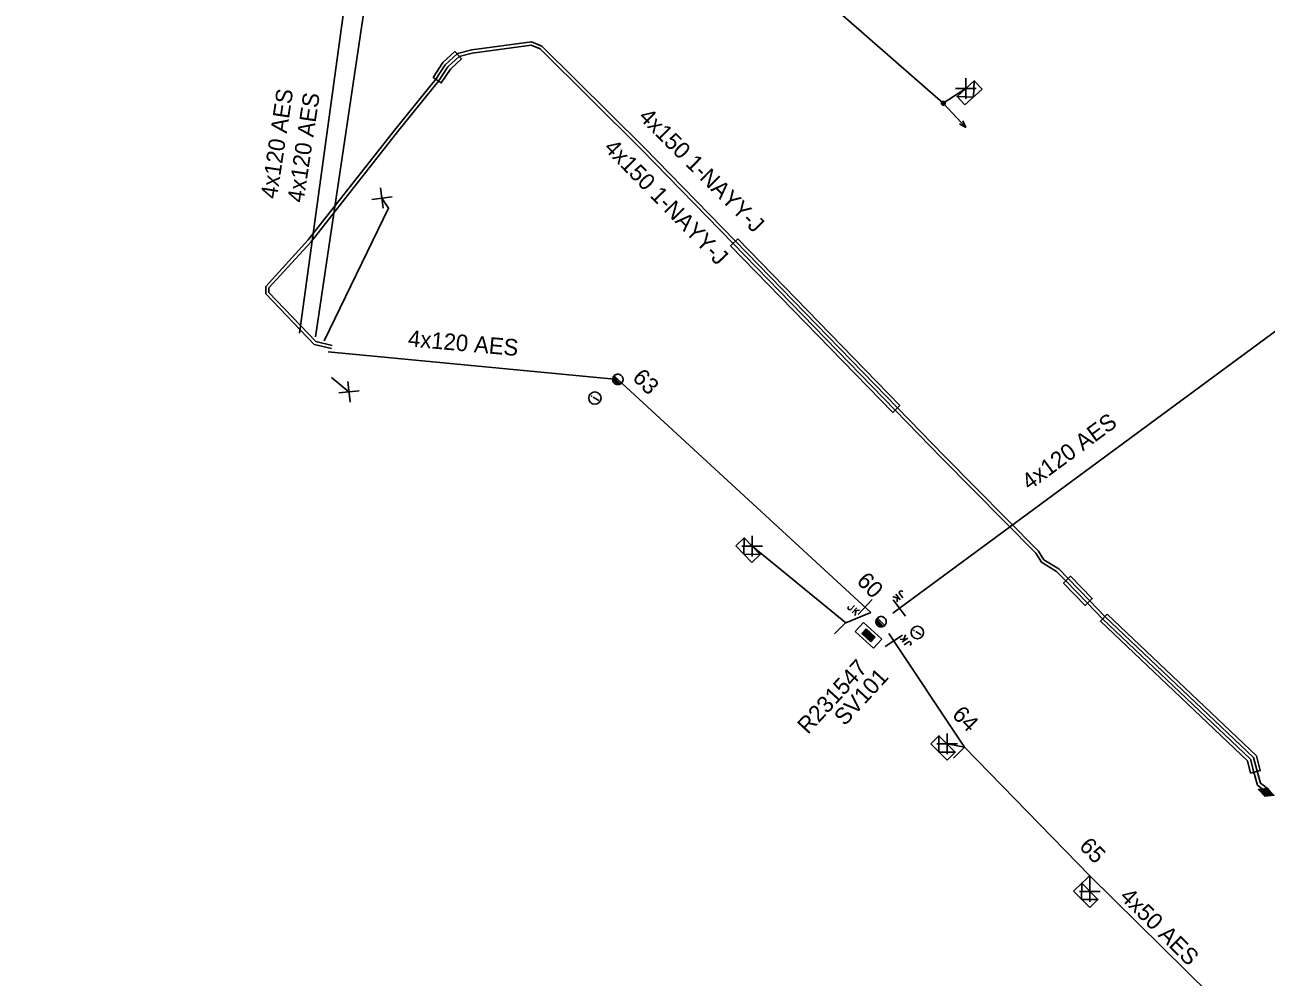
# Model space of a CAD drawing. Extents: x -544780 to -541582, y -1198995 to -1196551.
# Drawn here: x -543819.5 to -543744.4, y -1197448.1 to -1197390.4 of the extents above; entities that cross this region are included whole.
import ezdxf

# ---------------------------------------------------------------- set-up
doc = ezdxf.new("R2010")
doc.units = 0
for name, color, linetype in [('Vrstva 1', 7, 'Continuous'), ('Vrstva 10', 7, 'Continuous'), ('Vrstva 13', 7, 'Continuous'), ('Vrstva 14', 7, 'Continuous'), ('Vrstva 15', 7, 'Continuous'), ('Vrstva 18', 7, 'Continuous'), ('Vrstva 19', 7, 'Continuous'), ('Vrstva 2', 7, 'Continuous'), ('Vrstva 20', 7, 'Continuous'), ('Vrstva 28', 7, 'Continuous'), ('Vrstva 29', 7, 'Continuous'), ('Vrstva 30', 7, 'Continuous'), ('Vrstva 31', 7, 'Continuous'), ('Vrstva 34', 7, 'Continuous'), ('Vrstva 36', 7, 'Continuous'), ('Vrstva 4', 7, 'Continuous'), ('Vrstva 5', 7, 'Continuous'), ('Vrstva 50', 7, 'Continuous'), ('Vrstva 51', 7, 'Continuous'), ('Vrstva 54', 7, 'Continuous'), ('Vrstva 59', 7, 'Continuous'), ('Vrstva 6', 7, 'Continuous'), ('Vrstva 8', 7, 'Continuous'), ('Vrstva 9', 7, 'Continuous')]:
    doc.layers.add(name, color=color, linetype=linetype)

# ---------------------------------------------------------------- blocks, each defined once
blk = doc.blocks.new('NN440')
at = {"layer": 'Vrstva 2'}
for points in [[(0.63, 0), (0.63, 0.06), (0.62, 0.13), (0.6, 0.19), (0.58, 0.25), (0.55, 0.31), (0.51, 0.37), (0.47, 0.42), (0.42, 0.46), (0.37, 0.51), (0.32, 0.54), (0.26, 0.57), (0.2, 0.59), (0.13, 0.61), (0.07, 0.62), (0, 0.63), (-0.06, 0.62), (-0.13, 0.61), (-0.19, 0.59), (-0.26, 0.57), (-0.31, 0.54), (-0.37, 0.51), (-0.42, 0.46), (-0.47, 0.42), (-0.51, 0.37), (-0.54, 0.31), (-0.57, 0.25), (-0.6, 0.19), (-0.62, 0.13), (-0.63, 0.06), (-0.63, 0), (-0.63, -0.07), (-0.62, -0.14), (-0.6, -0.2), (-0.57, -0.26), (-0.54, -0.32), (-0.51, -0.37), (-0.47, -0.43), (-0.42, -0.47), (-0.37, -0.51), (-0.31, -0.55), (-0.26, -0.58), (-0.19, -0.6), (-0.13, -0.62), (-0.06, -0.63), (0, -0.63), (0.07, -0.63), (0.13, -0.62), (0.2, -0.6), (0.26, -0.58), (0.32, -0.55), (0.37, -0.51), (0.42, -0.47), (0.47, -0.43), (0.51, -0.37), (0.55, -0.32), (0.58, -0.26), (0.6, -0.2), (0.62, -0.14), (0.63, -0.07), (0.63, 0)], [(-0.63, 0), (0.63, 0)], [(-0.6, -0.18), (0.57, -0.18)], [(-0.51, -0.32), (0.5, -0.32)], [(-0.37, -0.47), (0.35, -0.47)]]:
    blk.add_lwpolyline(points, dxfattribs=at)
blk = doc.blocks.new('NN560')
at = {"layer": 'Vrstva 2'}
for points in [[(1.999, -0.001), (1.59, 0.141)], [(0, -0.001), (1.999, -0.001)], [(1.999, -0.001), (1.59, -0.134)]]:
    blk.add_lwpolyline(points, dxfattribs=at)
blk = doc.blocks.new('NN840')
at = {"layer": 'Vrstva 15'}
for points in [[(0.003, 0.619), (0.003, -0.631)], [(-0.745, -0.71), (-0.745, -0.66)], [(-0.73, -0.764), (-0.745, -0.71)], [(-0.538, -0.71), (-0.558, -0.764)], [(-0.538, -0.385), (-0.538, -0.71)], [(-0.332, -0.385), (-0.332, -0.798)], [(-0.332, -0.641), (-0.125, -0.385)], [(-0.263, -0.557), (-0.091, -0.798)], [(-0.657, -0.798), (-0.73, -0.764)], [(-0.627, -0.798), (-0.657, -0.798)], [(-0.558, -0.764), (-0.627, -0.798)]]:
    blk.add_lwpolyline(points, dxfattribs=at)
blk = doc.blocks.new('NN770')
at = {"layer": 'Vrstva 10'}
for p, q in [((0.002, 0.187), (0.002, 0.263)), ((0.002, -0.276), (0.002, 0.111))]:
    blk.add_line(p, q, dxfattribs=at)
blk.add_circle((0, -0.008), 0.375, dxfattribs=at)
blk = doc.blocks.new('NN870')
at = {"layer": 'Vrstva 4'}
for points in [[(0, -0.251), (0.5, 0.001), (0, 0.249), (-0.5, 0.001), (0, -0.251)], [(0.37, -0.003), (0, 0.186), (-0.362, 0.001), (0, -0.188), (0.37, -0.003)], [(0.245, -0.003), (0, 0.123), (-0.252, -0.003), (0, -0.125), (0.245, -0.003)], [(0.122, -0.003), (0, 0.06), (-0.13, -0.003), (0, -0.062), (0.122, -0.003)]]:
    blk.add_lwpolyline(points, dxfattribs=at)
blk = doc.blocks.new('NN800')
at = {"layer": 'Vrstva 1'}
for points in [[(-0.442, 0.442), (0.442, -0.442)], [(-0.442, -0.442), (0.442, 0.442)]]:
    blk.add_lwpolyline(points, dxfattribs=at)
blk = doc.blocks.new('NN620')
at = {"layer": 'Vrstva 8'}
for points in [[(0.752, 0.004), (-0.748, 0.004)], [(-0.748, 0.004), (-0.748, -0.746)], [(0.752, -0.746), (0.752, 0.004)], [(-0.748, -0.746), (0.752, -0.746)], [(0.368, -0.18), (-0.376, -0.18)], [(-0.376, -0.18), (-0.376, -0.558)], [(-0.376, -0.558), (0.368, -0.558)], [(0.321, -0.227), (-0.329, -0.227)], [(-0.329, -0.227), (-0.329, -0.51)], [(-0.329, -0.51), (0.321, -0.51)], [(0.274, -0.274), (-0.281, -0.274)], [(-0.281, -0.274), (-0.281, -0.463)], [(-0.281, -0.463), (0.274, -0.463)], [(0.227, -0.321), (-0.234, -0.321)], [(-0.234, -0.321), (-0.234, -0.416)], [(-0.234, -0.416), (0.227, -0.416)], [(-0.193, -0.369), (0.185, -0.369)], [(0.227, -0.416), (0.227, -0.321)], [(0.274, -0.463), (0.274, -0.274)], [(0.321, -0.51), (0.321, -0.227)], [(0.368, -0.558), (0.368, -0.18)]]:
    blk.add_lwpolyline(points, dxfattribs=at)
blk = doc.blocks.new('NN630')
at = {"layer": 'Vrstva 9'}
for points in [[(-0.003, -0.7), (-0.703, 0)], [(-0.703, -0.7), (-0.703, 0), (0.697, 0), (0.697, -0.7)], [(-0.703, -0.7), (0.697, -0.7)], [(-0.003, -0.7), (0.697, 0)]]:
    blk.add_lwpolyline(points, dxfattribs=at)
blk = doc.blocks.new('NN500')
at = {"layer": 'Vrstva 2'}
for points in [[(0, -0.24), (0.02, -0.23), (0.05, -0.23), (0.07, -0.22), (0.09, -0.22), (0.12, -0.2), (0.14, -0.19), (0.16, -0.18), (0.17, -0.16), (0.19, -0.14), (0.2, -0.12), (0.21, -0.1), (0.22, -0.07), (0.23, -0.05), (0.23, -0.02), (0.23, 0), (0.23, 0.02), (0.23, 0.05), (0.22, 0.07), (0.21, 0.1), (0.2, 0.12), (0.19, 0.14), (0.17, 0.16), (0.16, 0.17), (0.14, 0.19), (0.12, 0.2), (0.09, 0.21), (0.07, 0.22), (0.05, 0.23), (0.02, 0.23), (0, 0.23), (-0.03, 0.23), (-0.05, 0.23), (-0.07, 0.22), (-0.1, 0.21), (-0.12, 0.2), (-0.14, 0.19), (-0.16, 0.17), (-0.18, 0.16), (-0.19, 0.14), (-0.2, 0.12), (-0.22, 0.1), (-0.22, 0.07), (-0.23, 0.05), (-0.23, 0.02), (-0.24, 0), (-0.23, -0.02), (-0.23, -0.05), (-0.22, -0.07), (-0.22, -0.1), (-0.2, -0.12), (-0.19, -0.14), (-0.18, -0.16), (-0.16, -0.18), (-0.14, -0.19), (-0.12, -0.2), (-0.1, -0.22), (-0.07, -0.22), (-0.05, -0.23), (-0.03, -0.23), (0, -0.24)], [(0, -0.24), (0.02, -0.23), (0.05, -0.23), (0.07, -0.22), (0.09, -0.22), (0.12, -0.2), (0.14, -0.19), (0.16, -0.18), (0.17, -0.16), (0.19, -0.14), (0.2, -0.12), (0.21, -0.1), (0.22, -0.07), (0.23, -0.05), (0.23, -0.02), (0.23, 0), (0.23, 0.02), (0.23, 0.05), (0.22, 0.07), (0.21, 0.1), (0.2, 0.12), (0.19, 0.14), (0.17, 0.16), (0.16, 0.17), (0.14, 0.19), (0.12, 0.2), (0.09, 0.21), (0.07, 0.22), (0.05, 0.23), (0.02, 0.23), (0, 0.23), (-0.03, 0.23), (-0.05, 0.23), (-0.07, 0.22), (-0.1, 0.21), (-0.12, 0.2), (-0.14, 0.19), (-0.16, 0.17), (-0.18, 0.16), (-0.19, 0.14), (-0.2, 0.12), (-0.22, 0.1), (-0.22, 0.07), (-0.23, 0.05), (-0.23, 0.02), (-0.24, 0), (-0.23, -0.02), (-0.23, -0.05), (-0.22, -0.07), (-0.22, -0.1), (-0.2, -0.12), (-0.19, -0.14), (-0.18, -0.16), (-0.16, -0.18), (-0.14, -0.19), (-0.12, -0.2), (-0.1, -0.22), (-0.07, -0.22), (-0.05, -0.23), (-0.03, -0.23), (0, -0.24)], [(0, -0.21), (0.02, -0.2), (0.04, -0.2), (0.06, -0.2), (0.08, -0.19), (0.1, -0.18), (0.12, -0.17), (0.14, -0.15), (0.15, -0.14), (0.16, -0.12), (0.18, -0.1), (0.19, -0.08), (0.19, -0.06), (0.2, -0.04), (0.2, -0.02), (0.2, 0), (0.2, 0.02), (0.2, 0.04), (0.19, 0.06), (0.19, 0.08), (0.18, 0.1), (0.16, 0.12), (0.15, 0.14), (0.14, 0.15), (0.12, 0.17), (0.1, 0.18), (0.08, 0.19), (0.06, 0.19), (0.04, 0.2), (0.02, 0.2), (0, 0.2), (-0.02, 0.2), (-0.04, 0.2), (-0.06, 0.19), (-0.08, 0.19), (-0.1, 0.18), (-0.12, 0.17), (-0.14, 0.15), (-0.15, 0.14), (-0.17, 0.12), (-0.18, 0.1), (-0.19, 0.08), (-0.2, 0.06), (-0.2, 0.04), (-0.21, 0.02), (-0.21, 0), (-0.21, -0.02), (-0.2, -0.04), (-0.2, -0.06), (-0.19, -0.08), (-0.18, -0.1), (-0.17, -0.12), (-0.15, -0.14), (-0.14, -0.15), (-0.12, -0.17), (-0.1, -0.18), (-0.08, -0.19), (-0.06, -0.2), (-0.04, -0.2), (-0.02, -0.2), (0, -0.21)], [(0, -0.18), (0.02, -0.18), (0.04, -0.17), (0.05, -0.17), (0.07, -0.16), (0.09, -0.15), (0.1, -0.14), (0.12, -0.13), (0.13, -0.12), (0.14, -0.1), (0.15, -0.09), (0.16, -0.07), (0.17, -0.05), (0.17, -0.04), (0.17, -0.02), (0.17, 0), (0.17, 0.02), (0.17, 0.04), (0.17, 0.05), (0.16, 0.07), (0.15, 0.09), (0.14, 0.1), (0.13, 0.12), (0.12, 0.13), (0.1, 0.14), (0.09, 0.15), (0.07, 0.16), (0.05, 0.17), (0.04, 0.17), (0.02, 0.17), (0, 0.18), (-0.02, 0.17), (-0.04, 0.17), (-0.06, 0.17), (-0.07, 0.16), (-0.09, 0.15), (-0.1, 0.14), (-0.12, 0.13), (-0.13, 0.12), (-0.14, 0.1), (-0.15, 0.09), (-0.16, 0.07), (-0.17, 0.05), (-0.17, 0.04), (-0.18, 0.02), (-0.18, 0), (-0.18, -0.02), (-0.17, -0.04), (-0.17, -0.05), (-0.16, -0.07), (-0.15, -0.09), (-0.14, -0.1), (-0.13, -0.12), (-0.12, -0.13), (-0.1, -0.14), (-0.09, -0.15), (-0.07, -0.16), (-0.06, -0.17), (-0.04, -0.17), (-0.02, -0.18), (0, -0.18)], [(0, -0.15), (0.01, -0.15), (0.03, -0.14), (0.04, -0.14), (0.06, -0.13), (0.07, -0.13), (0.08, -0.12), (0.1, -0.11), (0.11, -0.1), (0.12, -0.09), (0.13, -0.07), (0.13, -0.06), (0.14, -0.05), (0.14, -0.03), (0.14, -0.02), (0.14, 0), (0.14, 0.01), (0.14, 0.03), (0.14, 0.04), (0.13, 0.06), (0.13, 0.07), (0.12, 0.09), (0.11, 0.1), (0.1, 0.11), (0.08, 0.12), (0.07, 0.13), (0.06, 0.13), (0.04, 0.14), (0.03, 0.14), (0.01, 0.14), (0, 0.15), (-0.02, 0.14), (-0.03, 0.14), (-0.05, 0.14), (-0.06, 0.13), (-0.07, 0.13), (-0.09, 0.12), (-0.1, 0.11), (-0.11, 0.1), (-0.12, 0.09), (-0.13, 0.07), (-0.13, 0.06), (-0.14, 0.04), (-0.14, 0.03), (-0.15, 0.01), (-0.15, 0), (-0.15, -0.02), (-0.14, -0.03), (-0.14, -0.05), (-0.13, -0.06), (-0.13, -0.07), (-0.12, -0.09), (-0.11, -0.1), (-0.1, -0.11), (-0.09, -0.12), (-0.07, -0.13), (-0.06, -0.13), (-0.05, -0.14), (-0.03, -0.14), (-0.02, -0.15), (0, -0.15)], [(0, -0.12), (0.01, -0.12), (0.02, -0.11), (0.03, -0.11), (0.05, -0.11), (0.06, -0.1), (0.07, -0.09), (0.08, -0.09), (0.09, -0.08), (0.09, -0.07), (0.1, -0.06), (0.11, -0.05), (0.11, -0.04), (0.11, -0.02), (0.11, -0.01), (0.12, 0), (0.11, 0.01), (0.11, 0.02), (0.11, 0.04), (0.11, 0.05), (0.1, 0.06), (0.09, 0.07), (0.09, 0.08), (0.08, 0.09), (0.07, 0.09), (0.06, 0.1), (0.05, 0.11), (0.03, 0.11), (0.02, 0.11), (0.01, 0.12), (0, 0.12), (-0.01, 0.12), (-0.03, 0.11), (-0.04, 0.11), (-0.05, 0.11), (-0.06, 0.1), (-0.07, 0.09), (-0.08, 0.09), (-0.09, 0.08), (-0.1, 0.07), (-0.1, 0.06), (-0.11, 0.05), (-0.11, 0.04), (-0.12, 0.02), (-0.12, 0.01), (-0.12, 0), (-0.12, -0.01), (-0.12, -0.02), (-0.11, -0.04), (-0.11, -0.05), (-0.1, -0.06), (-0.1, -0.07), (-0.09, -0.08), (-0.08, -0.09), (-0.07, -0.09), (-0.06, -0.1), (-0.05, -0.11), (-0.04, -0.11), (-0.03, -0.11), (-0.01, -0.12), (0, -0.12)], [(0, -0.09), (0.01, -0.09), (0.02, -0.09), (0.03, -0.08), (0.03, -0.08), (0.04, -0.08), (0.05, -0.07), (0.06, -0.07), (0.06, -0.06), (0.07, -0.05), (0.07, -0.04), (0.08, -0.04), (0.08, -0.03), (0.08, -0.02), (0.09, -0.01), (0.09, 0), (0.09, 0.01), (0.08, 0.02), (0.08, 0.03), (0.08, 0.03), (0.07, 0.04), (0.07, 0.05), (0.06, 0.06), (0.06, 0.06), (0.05, 0.07), (0.04, 0.07), (0.03, 0.08), (0.03, 0.08), (0.02, 0.08), (0.01, 0.09), (0, 0.09), (-0.01, 0.09), (-0.02, 0.08), (-0.03, 0.08), (-0.04, 0.08), (-0.04, 0.07), (-0.05, 0.07), (-0.06, 0.06), (-0.07, 0.06), (-0.07, 0.05), (-0.08, 0.04), (-0.08, 0.03), (-0.08, 0.03), (-0.09, 0.02), (-0.09, 0.01), (-0.09, 0), (-0.09, -0.01), (-0.09, -0.02), (-0.08, -0.03), (-0.08, -0.04), (-0.08, -0.04), (-0.07, -0.05), (-0.07, -0.06), (-0.06, -0.07), (-0.05, -0.07), (-0.04, -0.08), (-0.04, -0.08), (-0.03, -0.08), (-0.02, -0.09), (-0.01, -0.09), (0, -0.09)], [(0, -0.06), (0, -0.06), (0.01, -0.06), (0.02, -0.05), (0.02, -0.05), (0.03, -0.05), (0.03, -0.05), (0.04, -0.04), (0.04, -0.04), (0.05, -0.03), (0.05, -0.03), (0.05, -0.02), (0.05, -0.02), (0.05, -0.01), (0.06, -0.01), (0.06, 0), (0.06, 0.01), (0.05, 0.01), (0.05, 0.02), (0.05, 0.02), (0.05, 0.03), (0.05, 0.03), (0.04, 0.04), (0.04, 0.04), (0.03, 0.05), (0.03, 0.05), (0.02, 0.05), (0.02, 0.05), (0.01, 0.06), (0, 0.06), (0, 0.06), (-0.01, 0.06), (-0.01, 0.06), (-0.02, 0.05), (-0.02, 0.05), (-0.03, 0.05), (-0.03, 0.05), (-0.04, 0.04), (-0.04, 0.04), (-0.05, 0.03), (-0.05, 0.03), (-0.05, 0.02), (-0.06, 0.02), (-0.06, 0.01), (-0.06, 0.01), (-0.06, 0), (-0.06, -0.01), (-0.06, -0.01), (-0.06, -0.02), (-0.05, -0.02), (-0.05, -0.03), (-0.05, -0.03), (-0.04, -0.04), (-0.04, -0.04), (-0.03, -0.05), (-0.03, -0.05), (-0.02, -0.05), (-0.02, -0.05), (-0.01, -0.06), (-0.01, -0.06), (0, -0.06)], [(0, -0.03), (0, -0.03), (0, -0.03), (0.01, -0.03), (0.01, -0.03), (0.01, -0.02), (0.02, -0.02), (0.02, -0.02), (0.02, -0.02), (0.02, -0.02), (0.02, -0.01), (0.02, -0.01), (0.03, -0.01), (0.03, -0.01), (0.03, 0), (0.03, 0), (0.03, 0), (0.03, 0.01), (0.03, 0.01), (0.02, 0.01), (0.02, 0.01), (0.02, 0.02), (0.02, 0.02), (0.02, 0.02), (0.02, 0.02), (0.01, 0.02), (0.01, 0.02), (0.01, 0.03), (0, 0.03), (0, 0.03), (0, 0.03), (0, 0.03), (-0.01, 0.03), (-0.01, 0.03), (-0.01, 0.02), (-0.02, 0.02), (-0.02, 0.02), (-0.02, 0.02), (-0.02, 0.02), (-0.02, 0.02), (-0.03, 0.01), (-0.03, 0.01), (-0.03, 0.01), (-0.03, 0.01), (-0.03, 0), (-0.03, 0), (-0.03, 0), (-0.03, -0.01), (-0.03, -0.01), (-0.03, -0.01), (-0.03, -0.01), (-0.02, -0.02), (-0.02, -0.02), (-0.02, -0.02), (-0.02, -0.02), (-0.02, -0.02), (-0.01, -0.03), (-0.01, -0.03), (-0.01, -0.03), (0, -0.03), (0, -0.03)], [(0.23, 0), (0.7, 0)]]:
    blk.add_lwpolyline(points, dxfattribs=at)
blk = doc.blocks.new('NN510')
at = {"layer": 'Vrstva 2'}
blk.add_lwpolyline([(0.001, 0.002), (0.001, 0.939)], dxfattribs=at)

msp = doc.modelspace()

# ---------------------------------------------------------------- linework, layer by layer
at = {"layer": 'Vrstva 20'}
for points in [[(-543794.811, -1197393.616), (-543794.22, -1197392.714), (-543793.483, -1197392.039), (-543793.077, -1197392.481), (-543793.76, -1197393.106), (-543794.309, -1197393.944)], [(-543776.365, -1197403.391), (-543766.555, -1197413.471), (-543766.985, -1197413.889), (-543776.795, -1197403.809)], [(-543756.215, -1197423.81), (-543754.905, -1197425.15), (-543755.335, -1197425.57), (-543756.645, -1197424.23)], [(-543754.003, -1197426.092), (-543744.971, -1197434.672), (-543744.74, -1197435.565), (-543745.32, -1197435.715), (-543745.509, -1197434.988), (-543754.417, -1197426.528)]]:
    msp.add_lwpolyline(points, close=True, dxfattribs=at)
at = {"layer": 'Vrstva 5'}
for points in [[(-543800.963, -1197410.027), (-543802.002, -1197409.78), (-543804.94, -1197406.71), (-543804.94, -1197406.271), (-543802.366, -1197403.455), (-543797.038, -1197396.678), (-543794.641, -1197393.721), (-543794.067, -1197392.845), (-543793.329, -1197392.17), (-543792.469, -1197391.942), (-543788.848, -1197391.468), (-543788.214, -1197391.714), (-543782.059, -1197397.84), (-543776.508, -1197403.53), (-543766.698, -1197413.61), (-543763.879, -1197416.51), (-543758.162, -1197422.287), (-543757.828, -1197422.807), (-543756.937, -1197423.351), (-543756.358, -1197423.95), (-543755.048, -1197425.29), (-543754.139, -1197426.239), (-543745.15, -1197434.777), (-543744.934, -1197435.613), (-543744.723, -1197436.331), (-543744.229, -1197436.719)], [(-543800.917, -1197409.833), (-543801.898, -1197409.6), (-543804.74, -1197406.63), (-543804.74, -1197406.349), (-543802.214, -1197403.585), (-543796.882, -1197396.802), (-543794.479, -1197393.839), (-543793.913, -1197392.975), (-543793.231, -1197392.35), (-543792.431, -1197392.138), (-543788.872, -1197391.672), (-543788.326, -1197391.886), (-543782.201, -1197397.98), (-543776.652, -1197403.67), (-543766.842, -1197413.75), (-543764.021, -1197416.65), (-543758.318, -1197422.413), (-543757.972, -1197422.953), (-543757.063, -1197423.509), (-543756.502, -1197424.09), (-543755.192, -1197425.43), (-543754.281, -1197426.381), (-543745.33, -1197434.883), (-543745.126, -1197435.667), (-543744.897, -1197436.449), (-543744.416, -1197436.827), (-543744.38, -1197436.89)]]:
    msp.add_lwpolyline(points, dxfattribs=at)
at = {"layer": 'Vrstva 50'}
for points in [[(-543766.98, -1197426.038), (-543741.728, -1197407.43), (-543711.459, -1197387.37), (-543679.576, -1197366.233), (-543647.38, -1197345.27)], [(-543802.901, -1197409.09), (-543799.399, -1197383.654), (-543824.959, -1197361.139), (-543838.655, -1197349.487)], [(-543801.93, -1197409.309), (-543798.178, -1197384.05), (-543775.44, -1197359.32)], [(-543801.159, -1197410.232), (-543783.619, -1197411.89), (-543768.303, -1197425.994)], [(-543767.217, -1197427.271), (-543762.643, -1197434.154), (-543755.063, -1197441.93), (-543746.325, -1197450.559)]]:
    msp.add_lwpolyline(points, dxfattribs=at)
at = {"layer": 'Vrstva 54'}
for points in [[(-543762.643, -1197434.154), (-543763.69, -1197433.958)], [(-543755.063, -1197441.93), (-543755.048, -1197442.877)]]:
    msp.add_lwpolyline(points, dxfattribs=at)
at = {"layer": 'Vrstva 59'}
for points in [[(-543801.398, -1197409.565), (-543797.5, -1197401.522), (-543797.9, -1197400.917)], [(-543800.96, -1197411.773), (-543799.898, -1197412.64)]]:
    msp.add_lwpolyline(points, dxfattribs=at)
at = {"layer": 'Vrstva 8'}
for points in [[(-543777.786, -1197383.046), (-543763.924, -1197395.18), (-543762.567, -1197394.285)], [(-543768.303, -1197425.994), (-543769.831, -1197426.632), (-543775.492, -1197421.99)]]:
    msp.add_lwpolyline(points, dxfattribs=at)

# ---------------------------------------------------------------- block references
at = {"layer": 'Vrstva 13', "xscale": 0.5}
for name, p, yscale, rotation in [('NN500', (-543763.924, -1197395.18), 0.5, -47.001999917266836), ('NN440', (-543783.619, -1197411.89), 0.5, -45.121069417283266), ('NN440', (-543767.689, -1197426.559), 0.5000000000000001, -45.42231942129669)]:
    msp.add_blockref(name, p, dxfattribs=dict(at, yscale=yscale, rotation=rotation))
at = {"layer": 'Vrstva 13'}
for name, p, rotation in [('NN560', (-543763.924, -1197395.18), -47.001741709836), ('NN510', (-543769.831, -1197426.632), 134.25594167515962), ('NN510', (-543762.642, -1197434.154), 134.96126104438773), ('NN510', (-543755.063, -1197441.93), 134.2461527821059)]:
    msp.add_blockref(name, p, dxfattribs=dict(at, rotation=rotation))
at = {"layer": 'Vrstva 18'}
for p, rotation in [((-543768.646, -1197425.667), -43.016686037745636), ((-543766.578, -1197425.733), -143.31920286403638), ((-543766.917, -1197427.721), 123.60292222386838)]:
    msp.add_blockref('NN840', p, dxfattribs=dict(at, rotation=rotation))
at = {"layer": 'Vrstva 19', "rotation": 159.80019326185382}
msp.add_blockref('NN870', (-543744.38, -1197436.89), dxfattribs=at)
at = {"layer": 'Vrstva 28', "rotation": -42.6420000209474}
msp.add_blockref('NN620', (-543768.197, -1197427.111), dxfattribs=at)
at = {"layer": 'Vrstva 31'}
for p, rotation in [((-543762.567, -1197394.285), 42.61931941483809), ((-543775.492, -1197421.99), -45.744058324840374), ((-543763.69, -1197433.958), -45.038739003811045), ((-543755.048, -1197442.877), -45.75384721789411)]:
    msp.add_blockref('NN630', p, dxfattribs=dict(at, rotation=rotation))
at = {"layer": 'Vrstva 34'}
for p, rotation in [((-543762.567, -1197394.284), 45), ((-543797.9, -1197400.917), -37.56682220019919), ((-543799.898, -1197412.64), 140.76263254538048), ((-543775.492, -1197421.99), 45), ((-543763.69, -1197433.958), 44.99999995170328), ((-543755.048, -1197442.877), 44.99999995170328)]:
    msp.add_blockref('NN800', p, dxfattribs=dict(at, rotation=rotation))
at = {"layer": 'Vrstva 36'}
for p, rotation in [((-543785.019, -1197413.018), 58.516302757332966), ((-543765.5, -1197427.207), 58.51630274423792)]:
    msp.add_blockref('NN770', p, dxfattribs=dict(at, rotation=rotation))

# ---------------------------------------------------------------- texts
at = {"layer": 'Vrstva 14'}
for s, rotation, p in [('63', 314.879, (-543782.798, -1197411.844)), ('60', 314.578, (-543769.224, -1197424.156)), ('64', 314.961, (-543763.453, -1197432.251)), ('65', 314.246, (-543755.755, -1197440.206))]:
    msp.add_text(s, height=1, rotation=rotation, dxfattribs=at).set_placement(p)
at = {"layer": 'Vrstva 29'}
msp.add_text('R231547', height=1, rotation=47.358, dxfattribs=at).set_placement((-543772.117, -1197433.421))
at = {"layer": 'Vrstva 30'}
msp.add_text('SV101', height=1, rotation=47.358, dxfattribs=at).set_placement((-543769.894, -1197432.908))
at = {"layer": 'Vrstva 51'}
for s, rotation, p in [('4x120 AES', 81.43, (-543804.264, -1197401.002)), ('4x120 AES', 81.43, (-543802.654, -1197401.235)), ('4x120 AES', 354.968, (-543796.354, -1197409.892)), ('4x120 AES', 36.386, (-543758.709, -1197418.638)), ('4x50 AES', 315.36, (-543753.295, -1197443.264))]:
    msp.add_text(s, height=1, rotation=rotation, dxfattribs=at).set_placement(p)
at = {"layer": 'Vrstva 6'}
for rotation, p in [(315.135, (-543782.422, -1197396.067)), (314.281, (-543784.524, -1197397.933))]:
    msp.add_text('4x150 1-NAYY-J', height=1, rotation=rotation, dxfattribs=at).set_placement(p)

doc.saveas('drawing.dxf')
